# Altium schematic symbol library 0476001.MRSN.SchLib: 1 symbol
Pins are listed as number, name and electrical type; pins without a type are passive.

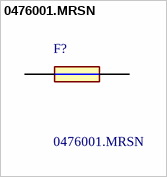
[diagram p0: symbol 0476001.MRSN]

## 0476001.MRSN
designator F?
Surface Mount Fuses 250VAC 1A .1575ohms 476 NANO2; Manufacturer_Name: LITTELFUSE; Geometry.Height: 2.94mm
footprint FUSC6127X294N
pins: 1, 2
